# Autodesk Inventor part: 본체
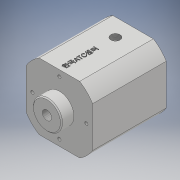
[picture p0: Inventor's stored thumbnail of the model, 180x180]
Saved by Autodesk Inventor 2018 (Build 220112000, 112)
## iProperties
Created: 2020-02
Part Number: 본체
Material: 일반
Document SubType Name: Modeling
Designer: USER
Density: 1 g/cm^3
Appearance: 기본값
Author: USER
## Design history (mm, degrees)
sketch "스케치1"
  geometry: L1 (19.551, 32)-(-19.551, 32); L2 (-32, 19.551)-(-32, -19.551); L3 (32, -19.551)-(32, 19.551); L4 (32, 32)-(-32, -32); L5 (-32, 32)-(32, -32); L6 (-19.551, -32)-(19.551, -32); A1 r 37.5 centre (0, 0) between (32, 19.551) and (19.551, 32); A2 r 37.5 centre (0, 0) between (-19.551, 32) and (-32, 19.551); A3 r 37.5 centre (0, 0) between (-32, -19.551) and (-19.551, -32); A4 r 37.5 centre (0, 0) between (19.551, -32) and (32, -19.551); 5 further points
  constraints: 12 end point, 8 point on circle, 6 midpoint, 4 centre point, 3 parallel, 2 horizontal, 2 vertical alignment, 1 coincident, 1 perpendicular
  dimensions: "d3" = 64 distance between parallel lines of L6 L1; "d4" = 64 distance between parallel lines of L2 L3; "d5" = 37.5 radius of A2; "d6" = 37.5 radius of A1; "d7" = 37.5 radius of A4; "d8" = 37.5 radius of A3
extrude "돌출1" new body sketch "스케치1" distance "d9" = 71; taper "d10" = 0 deg
sketch "스케치2"
  geometry: C1 r 14 at (0, 0); 1 further point
  constraints: 1 centre point, 1 coincident
  dimensions: "d11" = 28 diameter of C1
extrude "돌출2" join sketch "스케치2" distance "d12" = 12; taper "d13" = 0 deg
sketch "스케치3"
  geometry: C1 r 14 at (0, 0) reference; 2 further points
  constraints: 1 coincident
hole "구멍1" sketch "스케치3" at (0, 0) diameter "d14" = 8.917; stored, may be unused: countersink angle "d18" = 90 deg, drill point angle "d20" = 118 deg; dims "d15" = 14, "d16" = 4, "d17" = 2, "d19" = 17
sketch "스케치4"
  geometry: C1 r 14 at (0, 0) reference; A1 r 26 centre (0, 0) between (0, 26) and (26, 0); 3 further points
  constraints: 4 point on circle, 2 horizontal alignment, 2 vertical alignment, 1 centre point, 1 coincident
  dimensions: "d21" = 52 diameter of A1
hole "구멍2" sketch "스케치4" at (0, 26), (26, 0), (0, -26), (-26, 0) diameter "d22" = 3.242; stored, may be unused: countersink angle "d26" = 90 deg, drill point angle "d28" = 118 deg; dims "d23" = 10, "d24" = 4, "d25" = 2, "d27" = 12
sketch "스케치5"
  geometry: L1 (0, 0)-(39.102, 0) reference; 3 further points
  constraints: 1 midpoint, 1 vertical alignment, 1 other
  dimensions: "d29" = 20 distance from line of L1 point (19.551, 20)
feature "엠보싱1" sketch "스케치5" dims "d3" = 64, "d4" = 64, "d5" = 37.5, "d6" = 37.5, "d7" = 37.5, "d8" = 37.5, "d30" = 0.5, "d31" = 0
sketch "스케치6"
  geometry: L1 (0, 71)-(39.102, 71) reference; L2 (0, 0)-(39.102, 0) reference; 3 further points
  constraints: 1 midpoint, 1 vertical alignment
  dimensions: "d32" = 17 distance from line of L1 point (19.551, 54)
hole "구멍3" sketch "스케치6" at (19.551, 54) diameter "d33" = 8.917; stored, may be unused: countersink angle "d37" = 90 deg, drill point angle "d39" = 118 deg; dims "d34" = 6, "d35" = 4, "d36" = 2, "d38" = 9
sketch "스케치7"
  geometry: C1 r 20 at (0, 0); 1 further point
  constraints: 1 centre point, 1 coincident
  dimensions: "d40" = 40 diameter of C1
extrude "돌출3" cut sketch "스케치7" distance "d41" = 62; taper "d42" = 0 deg
sketch "스케치8"
  geometry: C1 r 2 at (0, 0); 1 further point
  constraints: 1 centre point, 1 coincident
  dimensions: "d43" = 4 diameter of C1
extrude "돌출4" cut sketch "스케치8" distance "d44" = 7; taper "d45" = 0 deg
sketch "스케치9"
  geometry: 1 further point
node "작업 평면1"
sketch "스케치10"
  geometry: L1 (-20, 0)-(20, 0) reference; L2 (19.551, -71)-(-19.551, -71) reference; C1 r 2 at (0, -17); 2 further points
  constraints: 1 centre point, 1 midpoint, 1 vertical alignment
  dimensions: "d46" = 4 diameter of C1; "d47" = 17 distance from line of C1.centre L1
extrude "돌출5" cut sketch "스케치10" distance "d48" = 3; taper "d49" = 0 deg
sketch "스케치11"
  geometry: 1 further point
sketch "스케치12"
  geometry: L1 (0, -19)-(0, -15) reference; C1 r 2 at (0, -17); 1 further point
  constraints: 1 centre point, 1 midpoint
  dimensions: "d50" = 4 diameter of C1
extrude "돌출6" cut sketch "스케치12" distance "d51" = 3; taper "d52" = 0 deg
sketch "스케치13"
  geometry: C1 r 20 at (0, 0) reference; C2 r 2 at (0, 0) reference; C3 r 26 at (0, 0); C4 r 1.621 at (0, 26) reference; 5 further points
  constraints: 4 coincident, 1 centre point, 4 other
  dimensions: "d53" = 52 diameter of C3; "d56" = 360 deg dimension on C3.centre point (0, 26) (derived)
hole "구멍4" sketch "스케치13" at (-22.517, -13), (22.517, -13), (0, 26) diameter "d58" = 3.242; stored, may be unused: countersink angle "d62" = 90 deg, drill point angle "d64" = 118 deg; dims "d59" = 10, "d60" = 4, "d61" = 2, "d63" = 12
chamfer "모따기1" distance "d65" = 1.8; stored, may be unused: second distance "d66" = 2, angle "d67" = 15 deg
sketch "스케치14"
  geometry: 1 further point
chamfer "모따기2" distance "d68" = 1; stored, may be unused: second distance "d69" = 2, angle "d70" = 45 deg
node "솔리드1"
node "투영된 루프1"
other parameters: "d0" = 75
